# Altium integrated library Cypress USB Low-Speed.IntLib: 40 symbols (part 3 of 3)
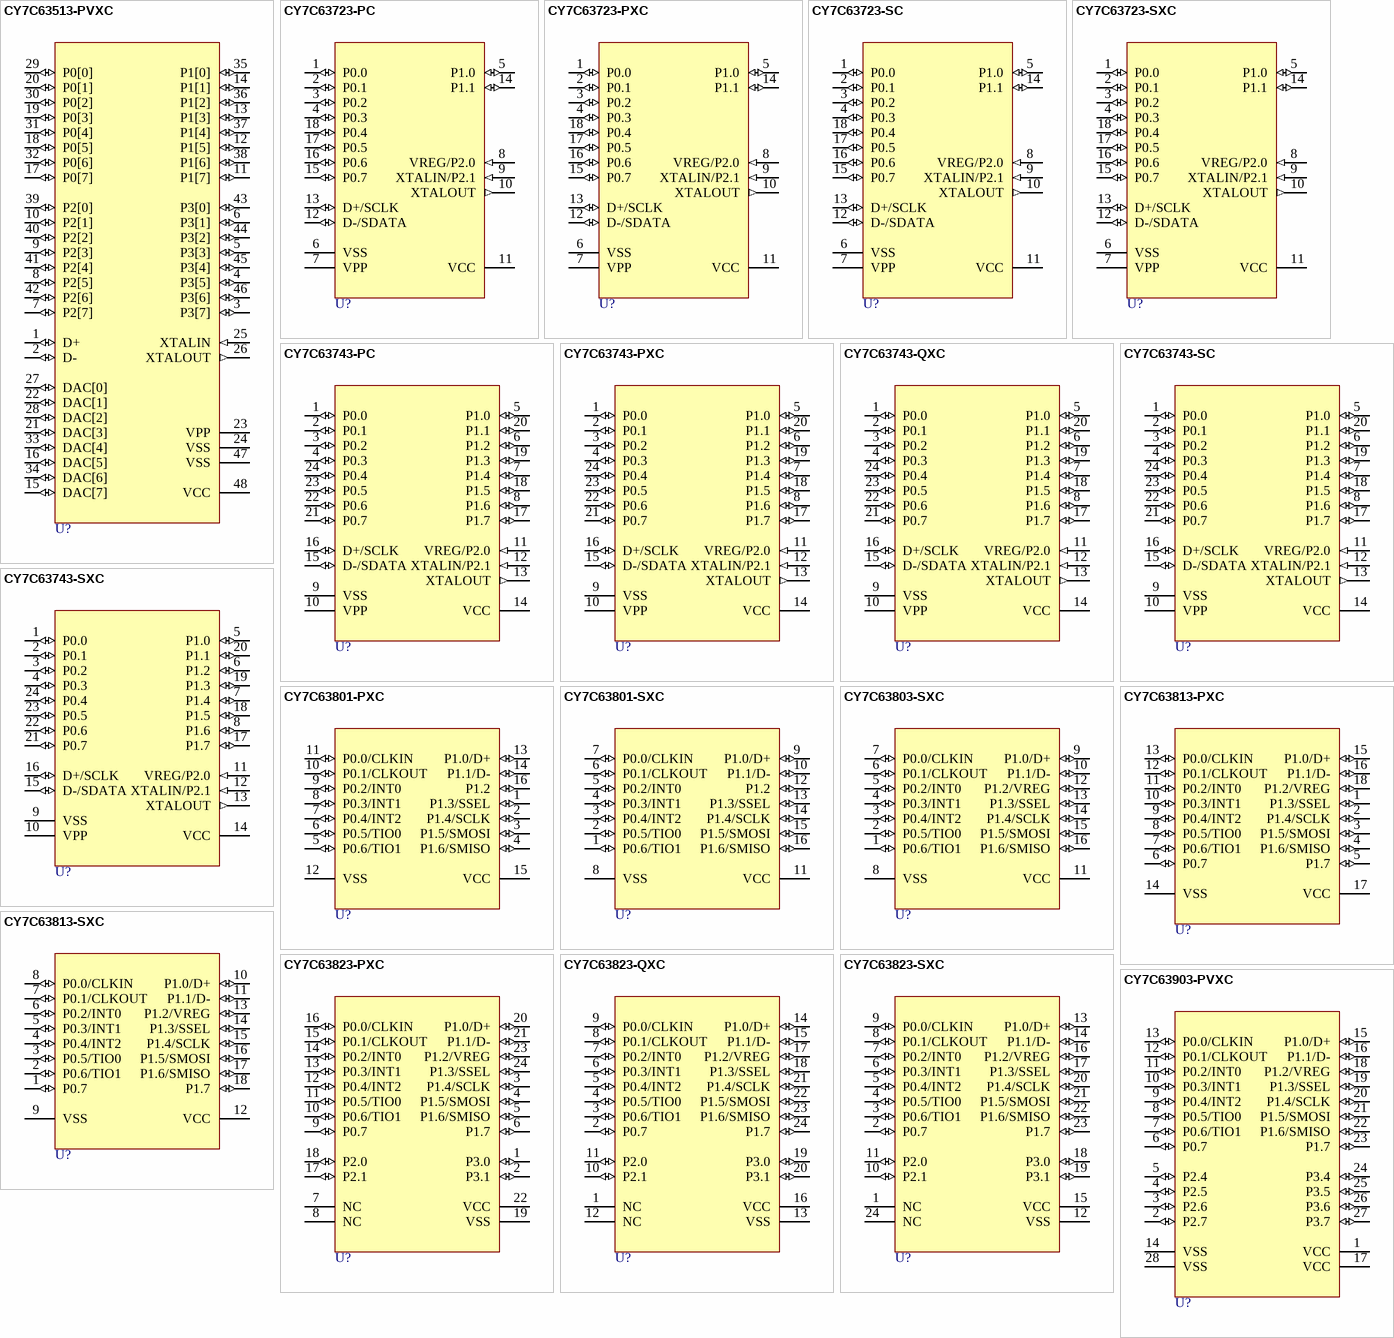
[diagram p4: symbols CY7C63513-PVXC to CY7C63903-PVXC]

## CY7C63823-SXC
designator U?
enCoRe II, Low-Speed USB Peripheral Controller, 8KB FLASH, 24-Pin SOIC,Commercial Grade, Pb-free
footprint S13_N (SOIC, 24-Leads, Body 15.4x7.5mm, Pitch 1.27mm, IPC Medium Density)
footprint S13_L (SOIC, 24-Leads, Body 15.4x7.5mm, Pitch 1.27mm, IPC High Density)
footprint S13_M (SOIC, 24-Leads, Body 15.4x7.5mm, Pitch 1.27mm, IPC Low Density)
pins: 1 NC "No connect", 2 P0.7 (io) "GPIO port 0 bit 7 - Configured individually", 3 P0.6/TIO1 (io) "GPIO port 0 bit 6 - Configured individually Alternate function Timer capture inputs or Timer output TIO1", 4 P0.5/TIO0 (io) "GPIO port 0 bit 5 - Configured individually Alternate function Timer capture inputs or Timer output TIO0", 5 P0.4/INT2 (io) "GPIO port 0 bit 4 - Configured individually Optional rising edge interrupt INT2", 6 P0.3/INT1 (io) "GPIO port 0 bit 3 - Configured individually Optional rising edge interrupt INT1", 7 P0.2/INT0 (io) "GPIO port 0 bit 2 - Configured individually Optional rising edge interrupt INT0", 8 P0.1/CLKOUT (io) "GPIO Port 0 bit 1 - Configured individually. Oscillator output when configured as Clock Out.", 9 P0.0/CLKIN (io) "GPIO Port 0 bit 0 - Configured individually. Oscillator input when configured as Clock In.", 10 P2.1 (io) "GPIO Port 2 bit 1", 11 P2.0 (io) "GPIO Port 2 bit 0", 12 VSS (power) "Ground", 13 P1.0/D+ (io) "GPIO Port 1 bit 0 / USB D+", 14 P1.1/D- (io) "GPIO Port 1 bit 1 / USB D-", 15 VCC (power) "Power", 16 P1.2/VREG (io) "GPIO Port 1 bit 2 - Configured individually. 3.3V if regulator is enabled.", 17 P1.3/SSEL (io) "GPIO Port 1 bit 3 - Configured individually. Alternate function is SSEL signal of the SPI bus TTL voltage thresholds", 18 P3.0 (io) "GPIO Port 3 bit 0", 19 P3.1 (io) "GPIO Port 3 bit 1", 20 P1.4/SCLK (io) "GPIO Port 1 bit 4 - Configured individually. Alternate function is SCLK signal of the SPI bus TTL voltage thresholds", 21 P1.5/SMOSI (io) "GPIO Port 1 bit 5 - Configured individually. Alternate function is SMOSI signal of the SPI bus TTL voltage thresholds", 22 P1.6/SMISO (io) "GPIO Port 1 bit 6 - Configured individually. Alternate function is SMISO signal of the SPI bus TTL voltage thresholds", 23 P1.7 (io) "GPIO Port 1 bit 7 - Configured individually. TTL voltage threshold.", 24 NC "No connect"

## CY7C63903-PVXC
designator U?
enCoRe II, Low-Speed USB Peripheral Controller, 8KB FLASH, 28-Pin SSOP, Commercial Grade, Pb-free
footprint O28_N (SOP, 28-Leads, Body 10.2x5.3mm, Pitch 0.65mm, IPC Medium Density)
footprint O28_L (SOP, 28-Leads, Body 10.2x5.3mm, Pitch 0.65mm, IPC High Density)
footprint O28_M (SOP, 28-Leads, Body 10.2x5.3mm, Pitch 0.65mm, IPC Low Density)
pins: 1 VCC (power) "Power", 2 P2.7 (io) "GPIO Port 2 bit 7 - Configured as a group (byte)", 3 P2.6 (io) "GPIO Port 2 bit 6 - Configured as a group (byte)", 4 P2.5 (io) "GPIO Port 2 bit 5 - Configured as a group (byte)", 5 P2.4 (io) "GPIO Port 2 bit 4 - Configured as a group (byte)", 6 P0.7 (io) "GPIO port 0 bit 7 - Configured individually", 7 P0.6/TIO1 (io) "GPIO port 0 bit 6 - Configured individually Alternate function Timer capture inputs or Timer output TIO1", 8 P0.5/TIO0 (io) "GPIO port 0 bit 5 - Configured individually Alternate function Timer capture inputs or Timer output TIO0", 9 P0.4/INT2 (io) "GPIO port 0 bit 4 - Configured individually Optional rising edge interrupt INT2", 10 P0.3/INT1 (io) "GPIO port 0 bit 3 - Configured individually Optional rising edge interrupt INT1", 11 P0.2/INT0 (io) "GPIO port 0 bit 2 - Configured individually Optional rising edge interrupt INT0", 12 P0.1/CLKOUT (io) "GPIO Port 0 bit 1 - Configured individually. Optional Clock Out when external crystal oscillator is disabled or crystal output drive when external crystal oscillator is enabled.", 13 P0.0/CLKIN (io) "GPIO Port 0 bit 0 - Configured individually. Optional Clock In when external crystal oscillator is disabled or crystal input when external crystal oscillator is enabled.", 14 VSS (power) "Ground", 15 P1.0/D+ (io) "GPIO Port 1 bit 0 / USB D+", 16 P1.1/D- (io) "GPIO Port 1 bit 1 / USB D-", 17 VCC (power) "Power", 18 P1.2/VREG (io) "GPIO Port 1 bit 2 - Configured individually. 3.3V if regulator is enabled.", 19 P1.3/SSEL (io) "GPIO Port 1 bit 3 - Configured individually. Alternate function is SSEL signal of the SPI bus TTL voltage thresholds", 20 P1.4/SCLK (io) "GPIO Port 1 bit 4 - Configured individually. Alternate function is SCLK signal of the SPI bus TTL voltage thresholds", 21 P1.5/SMOSI (io) "GPIO Port 1 bit 5 - Configured individually. Alternate function is SMOSI signal of the SPI bus TTL voltage thresholds", 22 P1.6/SMISO (io) "GPIO Port 1 bit 6 - Configured individually. Alternate function is SMISO signal of the SPI bus TTL voltage thresholds", 23 P1.7 (io) "GPIO Port 1 bit 7 - Configured individually. TTL voltage threshold.", 24 P3.4 (io) "GPIO Port 3 bit 4 - Configured as a group (byte)", 25 P3.5 (io) "GPIO Port 3 bit 5 - Configured as a group (byte)", 26 P3.6 (io) "GPIO Port 3 bit 6 - Configured as a group (byte)", 27 P3.7 (io) "GPIO Port 3 bit 7 - Configured as a group (byte)", 28 VSS (power) "Ground"

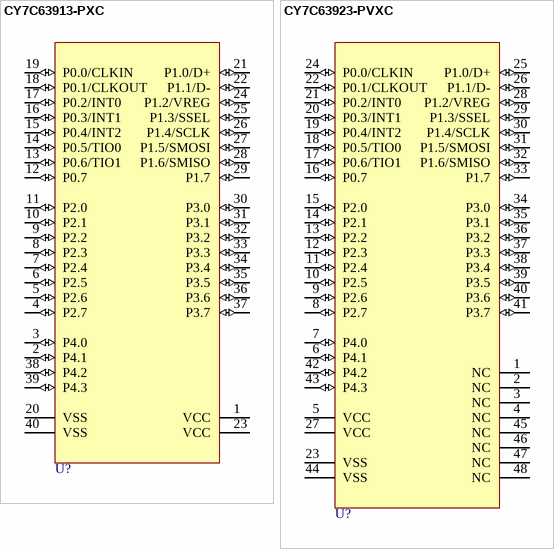
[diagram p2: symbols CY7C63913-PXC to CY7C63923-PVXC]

## CY7C63913-PXC
designator U?
enCoRe II, Low-Speed USB Peripheral Controller, 8KB FLASH, 40-Pin PDIP, Commercial Grade, Pb-free
footprint P17 (DIP, 40-Leads, Row Spacing 15.24mm, Pitch 2.54mm, Body 52.2x13.72mm)
pins: 1 VCC (power) "Power", 2 P4.1 (io) "GPIO Port 4 bit 1 - Configured as a group (nibble)", 3 P4.0 (io) "GPIO Port 4 bit 0 - Configured as a group (nibble)", 4 P2.7 (io) "GPIO Port 2 bit 7 - Configured as a group (byte)", 5 P2.6 (io) "GPIO Port 2 bit 6 - Configured as a group (byte)", 6 P2.5 (io) "GPIO Port 2 bit 5 - Configured as a group (byte)", 7 P2.4 (io) "GPIO Port 2 bit 4 - Configured as a group (byte)", 8 P2.3 (io) "GPIO Port 2 bit 3 - Configured as a group (byte)", 9 P2.2 (io) "GPIO Port 2 bit 2 - Configured as a group (byte)", 10 P2.1 (io) "GPIO Port 2 bit 1 - Configured as a group (byte)", 11 P2.0 (io) "GPIO Port 2 bit 0 - Configured as a group (byte)", 12 P0.7 (io) "GPIO port 0 bit 7 - Configured individually", 13 P0.6/TIO1 (io) "GPIO port 0 bit 6 - Configured individually Alternate function Timer capture inputs or Timer output TIO1", 14 P0.5/TIO0 (io) "GPIO port 0 bit 5 - Configured individually Alternate function Timer capture inputs or Timer output TIO0", 15 P0.4/INT2 (io) "GPIO port 0 bit 4 - Configured individually Optional rising edge interrupt INT2", 16 P0.3/INT1 (io) "GPIO port 0 bit 3 - Configured individually Optional rising edge interrupt INT1", 17 P0.2/INT0 (io) "GPIO port 0 bit 2 - Configured individually Optional rising edge interrupt INT0", 18 P0.1/CLKOUT (io) "GPIO Port 0 bit 1 - Configured individually. Optional Clock Out when external crystal oscillator is disabled or crystal output drive when external crystal oscillator is enabled.", 19 P0.0/CLKIN (io) "GPIO Port 0 bit 0 - Configured individually. Optional Clock In when external crystal oscillator is disabled or crystal input when external crystal oscillator is enabled.", 20 VSS (power) "Ground", 21 P1.0/D+ (io) "GPIO Port 1 bit 0 / USB D+", 22 P1.1/D- (io) "GPIO Port 1 bit 1 / USB D-", 23 VCC (power) "Power", 24 P1.2/VREG (io) "GPIO Port 1 bit 2 - Configured individually. 3.3V if regulator is enabled.", 25 P1.3/SSEL (io) "GPIO Port 1 bit 3 - Configured individually. Alternate function is SSEL signal of the SPI bus TTL voltage thresholds", 26 P1.4/SCLK (io) "GPIO Port 1 bit 4 - Configured individually. Alternate function is SCLK signal of the SPI bus TTL voltage thresholds", 27 P1.5/SMOSI (io) "GPIO Port 1 bit 5 - Configured individually. Alternate function is SMOSI signal of the SPI bus TTL voltage thresholds", 28 P1.6/SMISO (io) "GPIO Port 1 bit 6 - Configured individually. Alternate function is SMISO signal of the SPI bus TTL voltage thresholds", 29 P1.7 (io) "GPIO Port 1 bit 7 - Configured individually. TTL voltage threshold.", 30 P3.0 (io) "GPIO Port 3 bit 0 - Configured as a group (byte)", 31 P3.1 (io) "GPIO Port 3 bit 1 - Configured as a group (byte)", 32 P3.2 (io) "GPIO Port 3 bit 2 - Configured as a group (byte)", 33 P3.3 (io) "GPIO Port 3 bit 3 - Configured as a group (byte)", 34 P3.4 (io) "GPIO Port 3 bit 4 - Configured as a group (byte)", 35 P3.5 (io) "GPIO Port 3 bit 5 - Configured as a group (byte)", 36 P3.6 (io) "GPIO Port 3 bit 6 - Configured as a group (byte)", 37 P3.7 (io) "GPIO Port 3 bit 7 - Configured as a group (byte)", 38 P4.2 (io) "GPIO Port 4 bit 2 - Configured as a group (nibble)", 39 P4.3 (io) "GPIO Port 4 bit 3 - Configured as a group (nibble)", 40 VSS (power) "Ground"

## CY7C63923-PVXC
designator U?
enCoRe II, Low-Speed USB Peripheral Controller, 8KB FLASH, 48-Pin SSOP, Commercial Grade, Pb-free
footprint O48_N (SOP, 48-Leads, Body 15.9x7.5mm, Pitch 0.635mm, IPC Medium Density)
footprint O48_L (SOP, 48-Leads, Body 15.9x7.5mm, Pitch 0.635mm, IPC High Density)
footprint O48_M (SOP, 48-Leads, Body 15.9x7.5mm, Pitch 0.635mm, IPC Low Density)
pins: 1 NC "No connect", 2 NC "No connect", 3 NC "No connect", 4 NC "No connect", 5 VCC (power) "Power", 6 P4.1 (io) "GPIO Port 4 bit 1 - Configured as a group (nibble)", 7 P4.0 (io) "GPIO Port 4 bit 0 - Configured as a group (nibble)", 8 P2.7 (io) "GPIO Port 2 bit 7 - Configured as a group (byte)", 9 P2.6 (io) "GPIO Port 2 bit 6 - Configured as a group (byte)", 10 P2.5 (io) "GPIO Port 2 bit 5 - Configured as a group (byte)", 11 P2.4 (io) "GPIO Port 2 bit 4 - Configured as a group (byte)", 12 P2.3 (io) "GPIO Port 2 bit 3 - Configured as a group (byte)", 13 P2.2 (io) "GPIO Port 2 bit 2 - Configured as a group (byte)", 14 P2.1 (io) "GPIO Port 2 bit 1 - Configured as a group (byte)", 15 P2.0 (io) "GPIO Port 2 bit 0 - Configured as a group (byte)", 16 P0.7 (io) "GPIO port 0 bit 7 - Configured individually Not in 16 pin PDIP or SOIC package", 17 P0.6/TIO1 (io) "GPIO port 0 bit 6 - Configured individually Alternate function Timer capture inputs or Timer output TIO1", 18 P0.5/TIO0 (io) "GPIO port 0 bit 5 - Configured individually Alternate function Timer capture inputs or Timer output TIO0", 19 P0.4/INT2 (io) "GPIO port 0 bit 4 - Configured individually Optional rising edge interrupt INT2", 20 P0.3/INT1 (io) "GPIO port 0 bit 3 - Configured individually Optional rising edge interrupt INT1", 21 P0.2/INT0 (io) "GPIO port 0 bit 2 - Configured individually Optional rising edge interrupt INT0", 22 P0.1/CLKOUT (io) "GPIO Port 0 bit 1 - Configured individually. Optional Clock Out when external crystal oscillator is disabled or crystal output drive when external crystal oscillator is enabled.", 23 VSS (power) "Ground", 24 P0.0/CLKIN (io) "GPIO Port 0 bit 0 - Configured individually. Optional Clock In when external crystal oscillator is disabled or crystal input when external crystal oscillator is enabled.", 25 P1.0/D+ (io) "GPIO Port 1 bit 0 / USB D+", 26 P1.1/D- (io) "GPIO Port 1 bit 1 / USB D-", 27 VCC (power) "Power", 28 P1.2/VREG (io) "GPIO Port 1 bit 2 - Configured individually. 3.3V if regulator is enabled.", 29 P1.3/SSEL (io) "GPIO Port 1 bit 3 - Configured individually. Alternate function is SSEL signal of the SPI bus TTL voltage thresholds", 30 P1.4/SCLK (io) "GPIO Port 1 bit 4 - Configured individually. Alternate function is SCLK signal of the SPI bus TTL voltage thresholds", 31 P1.5/SMOSI (io) "GPIO Port 1 bit 5 - Configured individually. Alternate function is SMOSI signal of the SPI bus TTL voltage thresholds", 32 P1.6/SMISO (io) "GPIO Port 1 bit 6 - Configured individually. Alternate function is SMISO signal of the SPI bus TTL voltage thresholds", 33 P1.7 (io) "GPIO Port 1 bit 7 - Configured individually. TTL voltage threshold.", 34 P3.0 (io) "GPIO Port 3 bit 0 - Configured as a group (byte)", 35 P3.1 (io) "GPIO Port 3 bit 1 - Configured as a group (byte)", 36 P3.2 (io) "GPIO Port 3 bit 2 - Configured as a group (byte)", 37 P3.3 (io) "GPIO Port 3 bit 3 - Configured as a group (byte)", 38 P3.4 (io) "GPIO Port 3 bit 4 - Configured as a group (byte)", 39 P3.5 (io) "GPIO Port 3 bit 5 - Configured as a group (byte)", 40 P3.6 (io) "GPIO Port 3 bit 6 - Configured as a group (byte)", 41 P3.7 (io) "GPIO Port 3 bit 7 - Configured as a group (byte)", 42 P4.2 (io) "GPIO Port 4 bit 2 - Configured as a group (nibble)", 43 P4.3 (io) "GPIO Port 4 bit 3 - Configured as a group (nibble)", 44 VSS (power) "Ground", 45 NC "No connect", 46 NC "No connect", 47 NC "No connect", 48 NC "No connect"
